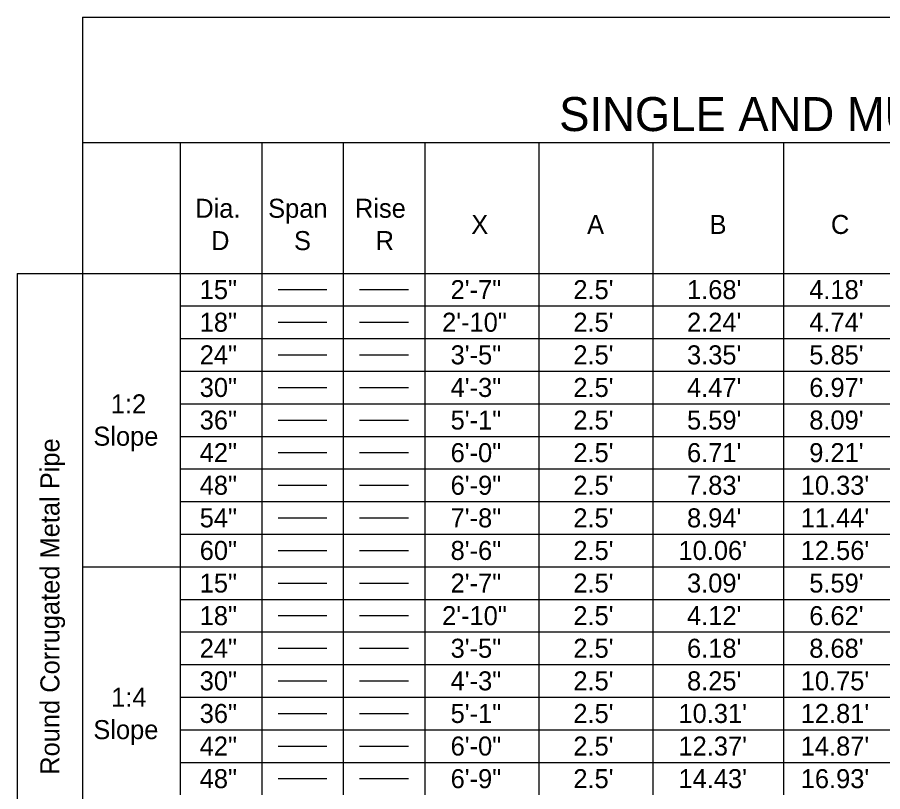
# Model space of a CAD drawing. Extents: x 1.7 to 14.4, y 0 to 7.8.
# Drawn here: x 1.7 to 4.886, y 4.902 to 7.752 of the extents above; entities that cross this region are included whole.
import ezdxf

# ---------------------------------------------------------------- set-up
doc = ezdxf.new("R2010")
doc.units = 0
doc.layers.add('Table', color=7, linetype='Continuous')

msp = doc.modelspace()

# ---------------------------------------------------------------- linework, layer by layer
at = {"layer": 'Table'}
for p, q in [((1.94, 7.7524), (13.46, 7.7524)), ((2.66, 6.75), (2.84, 6.75)), ((2.96, 6.75), (3.14, 6.75)), ((2.66, 6.63), (2.84, 6.63)), ((2.96, 6.63), (3.14, 6.63)), ((2.66, 6.51), (2.84, 6.51)), ((2.96, 6.51), (3.14, 6.51)), ((2.66, 6.39), (2.84, 6.39)), ((2.96, 6.39), (3.14, 6.39)), ((2.66, 6.27), (2.84, 6.27)), ((2.96, 6.27), (3.14, 6.27)), ((2.66, 6.15), (2.84, 6.15)), ((2.96, 6.15), (3.14, 6.15)), ((2.66, 6.03), (2.84, 6.03)), ((2.96, 6.03), (3.14, 6.03)), ((2.66, 5.91), (2.84, 5.91)), ((2.96, 5.91), (3.14, 5.91)), ((2.66, 5.79), (2.84, 5.79)), ((2.96, 5.79), (3.14, 5.79)), ((2.66, 5.67), (2.84, 5.67)), ((2.96, 5.67), (3.14, 5.67)), ((2.66, 5.55), (2.84, 5.55)), ((2.96, 5.55), (3.14, 5.55)), ((2.66, 5.43), (2.84, 5.43)), ((2.96, 5.43), (3.14, 5.43)), ((2.66, 5.31), (2.84, 5.31)), ((2.96, 5.31), (3.14, 5.31)), ((2.66, 5.19), (2.84, 5.19)), ((2.96, 5.19), (3.14, 5.19)), ((2.66, 5.07), (2.84, 5.07)), ((2.96, 5.07), (3.14, 5.07)), ((2.66, 4.95), (2.84, 4.95)), ((2.96, 4.95), (3.14, 4.95))]:
    msp.add_line(p, q, dxfattribs=at)
for points in [[(1.94, 7.7524), (1.94, 7.17), (1.94, 6.81), (1.94, 5.73), (1.94, 4.65), (1.94, 3.57), (1.94, 2.49)], [(13.46, 7.29), (11.78, 7.29), (10.1, 7.29), (8.42, 7.29), (8.06, 7.29), (6.38, 7.29), (6.02, 7.29), (5.66, 7.29), (5.3, 7.29), (4.94, 7.29), (4.52, 7.29), (4.04, 7.29), (3.62, 7.29), (3.2, 7.29), (2.9, 7.29), (2.6, 7.29), (2.3, 7.29), (1.94, 7.29)], [(2.3, 7.29), (2.3, 6.81), (2.3, 6.69), (2.3, 6.57), (2.3, 6.45), (2.3, 6.33), (2.3, 6.21), (2.3, 6.09), (2.3, 5.97), (2.3, 5.85), (2.3, 5.73), (2.3, 5.61), (2.3, 5.49), (2.3, 5.37), (2.3, 5.25), (2.3, 5.13), (2.3, 5.01), (2.3, 4.89)], [(2.6, 7.29), (2.6, 6.81), (2.6, 6.69), (2.6, 6.57), (2.6, 6.45), (2.6, 6.33), (2.6, 6.21), (2.6, 6.09), (2.6, 5.97), (2.6, 5.85), (2.6, 5.73), (2.6, 5.61), (2.6, 5.49), (2.6, 5.37), (2.6, 5.25), (2.6, 5.13), (2.6, 5.01), (2.6, 4.89)], [(2.9, 7.29), (2.9, 6.81), (2.9, 6.69), (2.9, 6.57), (2.9, 6.45), (2.9, 6.33), (2.9, 6.21), (2.9, 6.09), (2.9, 5.97), (2.9, 5.85), (2.9, 5.73), (2.9, 5.61), (2.9, 5.49), (2.9, 5.37), (2.9, 5.25), (2.9, 5.13), (2.9, 5.01), (2.9, 4.89)], [(3.2, 7.29), (3.2, 6.81), (3.2, 6.69), (3.2, 6.57), (3.2, 6.45), (3.2, 6.33), (3.2, 6.21), (3.2, 6.09), (3.2, 5.97), (3.2, 5.85), (3.2, 5.73), (3.2, 5.61), (3.2, 5.49), (3.2, 5.37), (3.2, 5.25), (3.2, 5.13), (3.2, 5.01), (3.2, 4.89)], [(3.62, 7.29), (3.62, 6.81), (3.62, 6.69), (3.62, 6.57), (3.62, 6.45), (3.62, 6.33), (3.62, 6.21), (3.62, 6.09), (3.62, 5.97), (3.62, 5.85), (3.62, 5.73), (3.62, 5.61), (3.62, 5.49), (3.62, 5.37), (3.62, 5.25), (3.62, 5.13), (3.62, 5.01), (3.62, 4.89)], [(4.04, 7.29), (4.04, 6.81), (4.04, 6.69), (4.04, 6.57), (4.04, 6.45), (4.04, 6.33), (4.04, 6.21), (4.04, 6.09), (4.04, 5.97), (4.04, 5.85), (4.04, 5.73), (4.04, 5.61), (4.04, 5.49), (4.04, 5.37), (4.04, 5.25), (4.04, 5.13), (4.04, 5.01), (4.04, 4.89)], [(4.52, 7.29), (4.52, 6.81), (4.52, 6.69), (4.52, 6.57), (4.52, 6.45), (4.52, 6.33), (4.52, 6.21), (4.52, 6.09), (4.52, 5.97), (4.52, 5.85), (4.52, 5.73), (4.52, 5.61), (4.52, 5.49), (4.52, 5.37), (4.52, 5.25), (4.52, 5.13), (4.52, 5.01), (4.52, 4.89)], [(1.7, 6.81), (1.94, 6.81), (2.3, 6.81), (2.6, 6.81), (2.9, 6.81), (3.2, 6.81), (3.62, 6.81), (4.04, 6.81), (4.52, 6.81), (4.94, 6.81), (5.3, 6.81), (5.66, 6.81), (6.02, 6.81), (6.38, 6.81), (6.8, 6.81), (7.22, 6.81), (7.64, 6.81), (8.06, 6.81), (8.42, 6.81)], [(1.7, 6.81), (1.7, 4.65), (1.7, 2.49)], [(2.3, 6.69), (2.6, 6.69), (2.9, 6.69), (3.2, 6.69), (3.62, 6.69), (4.04, 6.69), (4.52, 6.69), (4.94, 6.69), (5.3, 6.69), (5.66, 6.69), (6.02, 6.69), (6.38, 6.69), (6.8, 6.69), (7.22, 6.69), (7.64, 6.69), (8.06, 6.69), (8.42, 6.69)], [(2.3, 6.57), (2.6, 6.57), (2.9, 6.57), (3.2, 6.57), (3.62, 6.57), (4.04, 6.57), (4.52, 6.57), (4.94, 6.57), (5.3, 6.57), (5.66, 6.57), (6.02, 6.57), (6.38, 6.57), (6.8, 6.57), (7.22, 6.57), (7.64, 6.57), (8.06, 6.57), (8.42, 6.57)], [(2.3, 6.45), (2.6, 6.45), (2.9, 6.45), (3.2, 6.45), (3.62, 6.45), (4.04, 6.45), (4.52, 6.45), (4.94, 6.45), (5.3, 6.45), (5.66, 6.45), (6.02, 6.45), (6.38, 6.45), (6.8, 6.45), (7.22, 6.45), (7.64, 6.45), (8.06, 6.45), (8.42, 6.45)], [(2.3, 6.33), (2.6, 6.33), (2.9, 6.33), (3.2, 6.33), (3.62, 6.33), (4.04, 6.33), (4.52, 6.33), (4.94, 6.33), (5.3, 6.33), (5.66, 6.33), (6.02, 6.33), (6.38, 6.33), (6.8, 6.33), (7.22, 6.33), (7.64, 6.33), (8.06, 6.33), (8.42, 6.33)], [(2.3, 6.21), (2.6, 6.21), (2.9, 6.21), (3.2, 6.21), (3.62, 6.21), (4.04, 6.21), (4.52, 6.21), (4.94, 6.21), (5.3, 6.21), (5.66, 6.21), (6.02, 6.21), (6.38, 6.21), (6.8, 6.21), (7.22, 6.21), (7.64, 6.21), (8.06, 6.21), (8.42, 6.21)], [(2.3, 6.09), (2.6, 6.09), (2.9, 6.09), (3.2, 6.09), (3.62, 6.09), (4.04, 6.09), (4.52, 6.09), (4.94, 6.09), (5.3, 6.09), (5.66, 6.09), (6.02, 6.09), (6.38, 6.09), (6.8, 6.09), (7.22, 6.09), (7.64, 6.09), (8.06, 6.09), (8.42, 6.09)], [(2.3, 5.97), (2.6, 5.97), (2.9, 5.97), (3.2, 5.97), (3.62, 5.97), (4.04, 5.97), (4.52, 5.97), (4.94, 5.97), (5.3, 5.97), (5.66, 5.97), (6.02, 5.97), (6.38, 5.97), (6.8, 5.97), (7.22, 5.97), (7.64, 5.97), (8.06, 5.97), (8.42, 5.97)], [(2.3, 5.85), (2.6, 5.85), (2.9, 5.85), (3.2, 5.85), (3.62, 5.85), (4.04, 5.85), (4.52, 5.85), (4.94, 5.85), (5.3, 5.85), (5.66, 5.85), (6.02, 5.85), (6.38, 5.85), (6.8, 5.85), (7.22, 5.85), (7.64, 5.85), (8.06, 5.85), (8.42, 5.85)], [(1.94, 5.73), (2.3, 5.73), (2.6, 5.73), (2.9, 5.73), (3.2, 5.73), (3.62, 5.73), (4.04, 5.73), (4.52, 5.73), (4.94, 5.73), (5.3, 5.73), (5.66, 5.73), (6.02, 5.73), (6.38, 5.73), (6.8, 5.73), (7.22, 5.73), (7.64, 5.73), (8.06, 5.73), (8.42, 5.73)], [(2.3, 5.61), (2.6, 5.61), (2.9, 5.61), (3.2, 5.61), (3.62, 5.61), (4.04, 5.61), (4.52, 5.61), (4.94, 5.61), (5.3, 5.61), (5.66, 5.61), (6.02, 5.61), (6.38, 5.61), (6.8, 5.61), (7.22, 5.61), (7.64, 5.61), (8.06, 5.61), (8.42, 5.61)], [(2.3, 5.49), (2.6, 5.49), (2.9, 5.49), (3.2, 5.49), (3.62, 5.49), (4.04, 5.49), (4.52, 5.49), (4.94, 5.49), (5.3, 5.49), (5.66, 5.49), (6.02, 5.49), (6.38, 5.49), (6.8, 5.49), (7.22, 5.49), (7.64, 5.49), (8.06, 5.49), (8.42, 5.49)], [(2.3, 5.37), (2.6, 5.37), (2.9, 5.37), (3.2, 5.37), (3.62, 5.37), (4.04, 5.37), (4.52, 5.37), (4.94, 5.37), (5.3, 5.37), (5.66, 5.37), (6.02, 5.37), (6.38, 5.37), (6.8, 5.37), (7.22, 5.37), (7.64, 5.37), (8.06, 5.37), (8.42, 5.37)], [(2.3, 5.25), (2.6, 5.25), (2.9, 5.25), (3.2, 5.25), (3.62, 5.25), (4.04, 5.25), (4.52, 5.25), (4.94, 5.25), (5.3, 5.25), (5.66, 5.25), (6.02, 5.25), (6.38, 5.25), (6.8, 5.25), (7.22, 5.25), (7.64, 5.25), (8.06, 5.25), (8.42, 5.25)], [(2.3, 5.13), (2.6, 5.13), (2.9, 5.13), (3.2, 5.13), (3.62, 5.13), (4.04, 5.13), (4.52, 5.13), (4.94, 5.13), (5.3, 5.13), (5.66, 5.13), (6.02, 5.13), (6.38, 5.13), (6.8, 5.13), (7.22, 5.13), (7.64, 5.13), (8.06, 5.13), (8.42, 5.13)], [(2.3, 5.01), (2.6, 5.01), (2.9, 5.01), (3.2, 5.01), (3.62, 5.01), (4.04, 5.01), (4.52, 5.01), (4.94, 5.01), (5.3, 5.01), (5.66, 5.01), (6.02, 5.01), (6.38, 5.01), (6.8, 5.01), (7.22, 5.01), (7.64, 5.01), (8.06, 5.01), (8.42, 5.01)]]:
    msp.add_lwpolyline(points, dxfattribs=at)

# ---------------------------------------------------------------- texts
for s, height, p in [('SINGLE AND MULTIPLE CORRUGATED METAL PIPE DIMENSIONS AND QUANTITIES', 0.125, (3.6948, 7.3337)), ('Dia.', 0.07, (2.3552, 7.0145)), ('Span', 0.07, (2.6234, 7.0145)), ('Rise', 0.07, (2.9431, 7.0145)), ('X', 0.07, (3.3712, 6.955)), ('A', 0.07, (3.7975, 6.955)), ('B', 0.07, (4.2483, 6.955)), ('C', 0.07, (4.6952, 6.955)), ('D', 0.07, (2.4134, 6.8955)), ('S', 0.07, (2.7186, 6.8955)), ('R', 0.07, (3.0192, 6.8955)), ('1:2', 0.07, (2.0441, 6.2945)), ('Slope', 0.07, (1.98, 6.1755)), ('1:4', 0.07, (2.0455, 5.2145)), ('Slope', 0.07, (1.98, 5.0955))]:
    msp.add_text(s, height=height, dxfattribs=at).set_placement(p)
for s, rotation, p in [('2\'-7"', 0, (3.2951, 6.715)), ("2.5'", 0, (3.7469, 6.715)), ("1.68'", 0, (4.1654, 6.715)), ("4.18'", 0, (4.6154, 6.715)), ('15"', 0, (2.3715, 6.715)), ('18"', 0, (2.3715, 6.595)), ('2\'-10"', 0, (3.2637, 6.595)), ("2.5'", 0, (3.7469, 6.595)), ("2.24'", 0, (4.1654, 6.595)), ("4.74'", 0, (4.6154, 6.595)), ('24"', 0, (2.3715, 6.475)), ('3\'-5"', 0, (3.2951, 6.475)), ("2.5'", 0, (3.7469, 6.475)), ("3.35'", 0, (4.1654, 6.475)), ("5.85'", 0, (4.6154, 6.475)), ('30"', 0, (2.3715, 6.355)), ('4\'-3"', 0, (3.2951, 6.355)), ("2.5'", 0, (3.7469, 6.355)), ("4.47'", 0, (4.1654, 6.355)), ("6.97'", 0, (4.6154, 6.355)), ('36"', 0, (2.3715, 6.235)), ('5\'-1"', 0, (3.2951, 6.235)), ("2.5'", 0, (3.7469, 6.235)), ("5.59'", 0, (4.1654, 6.235)), ("8.09'", 0, (4.6154, 6.235)), ('Round Corrugated Metal Pipe', 90, (1.855, 4.9643)), ('42"', 0, (2.3715, 6.115)), ('6\'-0"', 0, (3.2951, 6.115)), ("2.5'", 0, (3.7469, 6.115)), ("6.71'", 0, (4.1654, 6.115)), ("9.21'", 0, (4.6154, 6.115)), ('48"', 0, (2.3715, 5.995)), ('6\'-9"', 0, (3.2951, 5.995)), ("2.5'", 0, (3.7469, 5.995)), ("7.83'", 0, (4.1654, 5.995)), ("10.33'", 0, (4.584, 5.995)), ('54"', 0, (2.3715, 5.875)), ('7\'-8"', 0, (3.2951, 5.875)), ("2.5'", 0, (3.7469, 5.875)), ("8.94'", 0, (4.1654, 5.875)), ("11.44'", 0, (4.584, 5.875)), ('60"', 0, (2.3715, 5.755)), ('8\'-6"', 0, (3.2951, 5.755)), ("2.5'", 0, (3.7469, 5.755)), ("10.06'", 0, (4.134, 5.755)), ("12.56'", 0, (4.584, 5.755)), ('15"', 0, (2.3715, 5.635)), ('2\'-7"', 0, (3.2951, 5.635)), ("2.5'", 0, (3.7469, 5.635)), ("3.09'", 0, (4.1654, 5.635)), ("5.59'", 0, (4.6154, 5.635)), ('18"', 0, (2.3715, 5.515)), ('2\'-10"', 0, (3.2637, 5.515)), ("2.5'", 0, (3.7469, 5.515)), ("4.12'", 0, (4.1654, 5.515)), ("6.62'", 0, (4.6154, 5.515)), ('24"', 0, (2.3715, 5.395)), ('3\'-5"', 0, (3.2951, 5.395)), ("2.5'", 0, (3.7469, 5.395)), ("6.18'", 0, (4.1654, 5.395)), ("8.68'", 0, (4.6154, 5.395)), ('30"', 0, (2.3715, 5.275)), ('4\'-3"', 0, (3.2951, 5.275)), ("2.5'", 0, (3.7469, 5.275)), ("8.25'", 0, (4.1654, 5.275)), ("10.75'", 0, (4.584, 5.275)), ('36"', 0, (2.3715, 5.155)), ('5\'-1"', 0, (3.2951, 5.155)), ("2.5'", 0, (3.7469, 5.155)), ("10.31'", 0, (4.134, 5.155)), ("12.81'", 0, (4.584, 5.155)), ('42"', 0, (2.3715, 5.035)), ('6\'-0"', 0, (3.2951, 5.035)), ("2.5'", 0, (3.7469, 5.035)), ("12.37'", 0, (4.134, 5.035)), ("14.87'", 0, (4.584, 5.035)), ('48"', 0, (2.3715, 4.915)), ('6\'-9"', 0, (3.2951, 4.915)), ("2.5'", 0, (3.7469, 4.915)), ("14.43'", 0, (4.134, 4.915)), ("16.93'", 0, (4.584, 4.915))]:
    msp.add_text(s, height=0.07, rotation=rotation, dxfattribs=at).set_placement(p)

doc.saveas('drawing.dxf')
